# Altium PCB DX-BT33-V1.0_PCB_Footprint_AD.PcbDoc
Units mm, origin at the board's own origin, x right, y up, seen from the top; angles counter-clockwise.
Board outline 152.4 x 101.6 mm, 2 copper layers (Top Layer, Bottom Layer); 1 components, 15 nets, 26 pads, 0 vias.
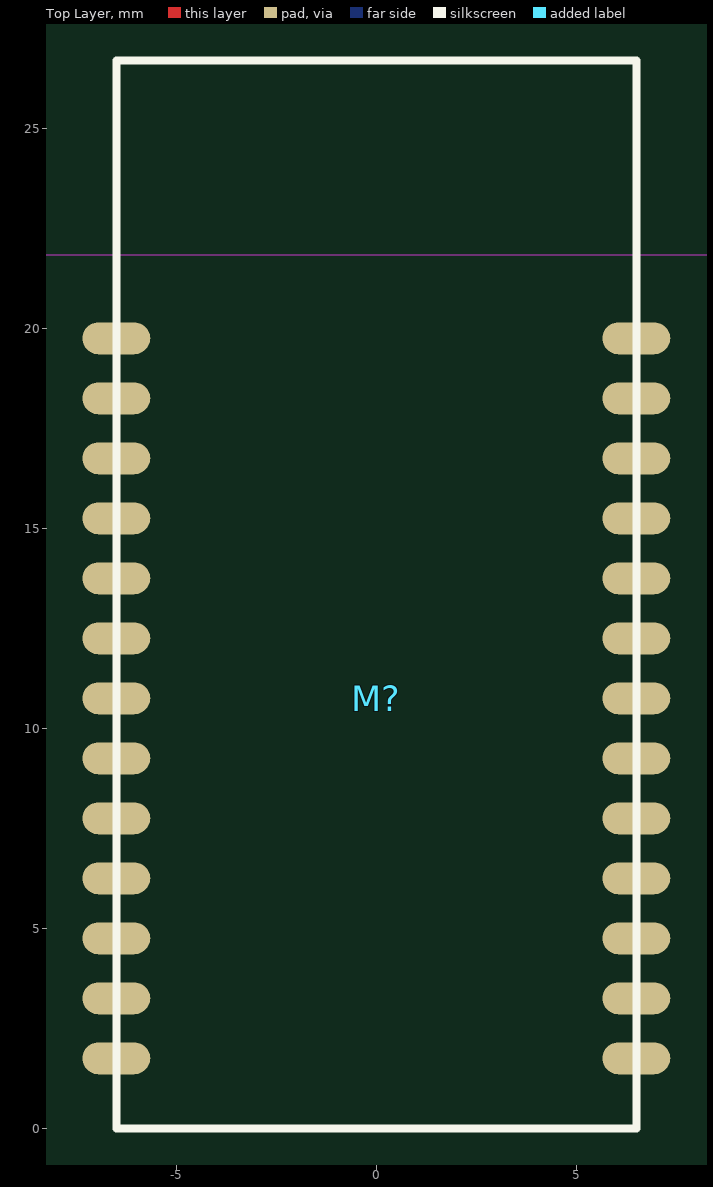
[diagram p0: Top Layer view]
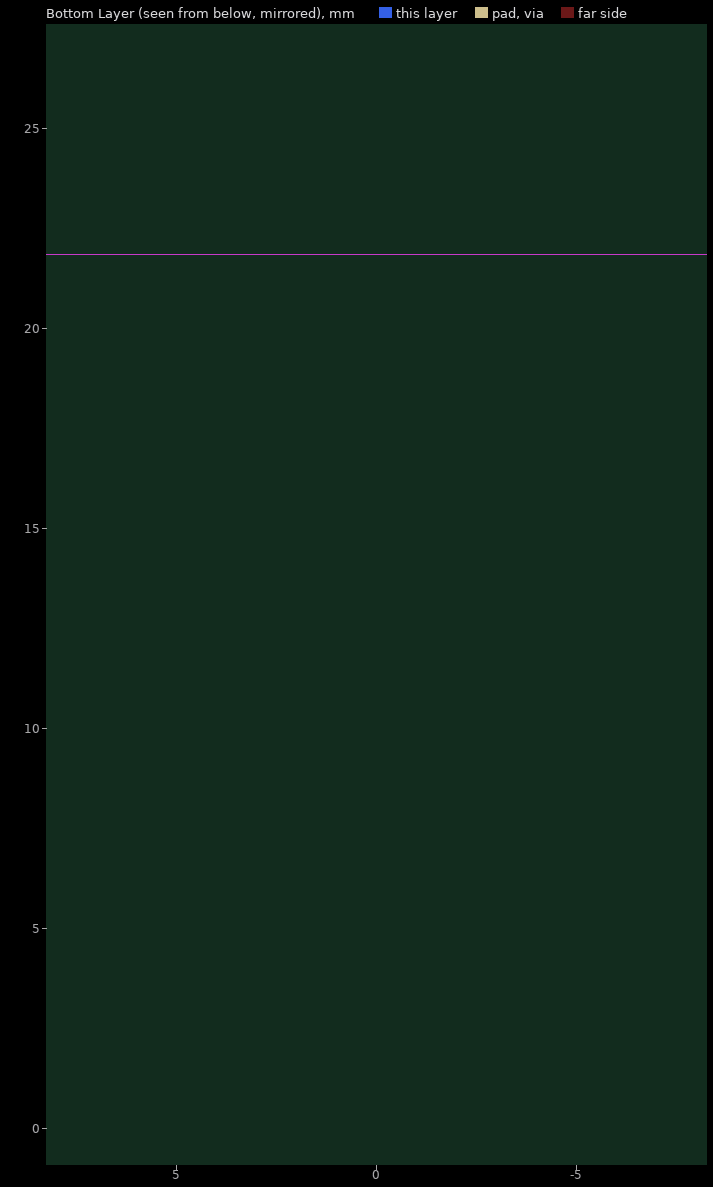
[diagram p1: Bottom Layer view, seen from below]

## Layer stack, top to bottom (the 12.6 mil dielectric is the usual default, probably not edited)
Top Solder: solder mask 0.0102, Solder Resist, Dk 3.5
Top Layer: signal copper 0.0356
Dielectric 1: dielectric 0.32, FR-4, Dk 4.8
Bottom Layer: signal copper 0.0356
Bottom Solder: solder mask 0.0102, Solder Resist, Dk 3.5

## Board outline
-72.857,-39.865 79.543,-39.865 79.543,61.735 -72.857,61.735

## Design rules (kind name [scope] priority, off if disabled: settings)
Clearance [All] p1: gap=0.254 ignorepadtopadclearanceinfootprint=FALSE except(0: Arc-Hole Track-Hole SMDPad-Hole THPad-Hole Via-Hole Fill-Hole Poly-Hole Region-Hole Text-Hole)
PolygonConnect [All] p1: connectstyle=Relief reliefconductorwidth=0.254 reliefentries=4 polygonreliefangle="90 Angle" airgapwidth=0.254
RoutingVias [All] p1: holewidth=0.711 width=1.27 viastyle="Through Hole" minholewidth=0.711 minwidth=1.27 maxholewidth=0.711 maxwidth=1.27
SolderMaskExpansion [All] p1: expansion=0.102 istentingtop=FALSE
Width [All] p1: maxlimit=0.254 minlimit=0.254 preferedwidth=0.254
30 further rules are at their usual default settings.

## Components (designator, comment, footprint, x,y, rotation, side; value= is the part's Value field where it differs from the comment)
M? "DX-BT33" DX-BT33 0,0 r0 top

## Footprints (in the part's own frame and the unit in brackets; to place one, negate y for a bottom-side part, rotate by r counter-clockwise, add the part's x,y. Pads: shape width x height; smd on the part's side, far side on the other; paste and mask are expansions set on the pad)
DX-BT33 [mm]
  oval 1.7x0.8 smd: 1(-6.5,19.75) 2(-6.5,18.25) 3(-6.5,16.75) 4(-6.5,15.25) 5(-6.5,13.75) 6(-6.5,12.25) 7(-6.5,10.75) 8(-6.5,9.25) 9(-6.5,7.75) 10(-6.5,6.25) 11(-6.5,4.75) 12(-6.5,3.25) 13(-6.5,1.75) 14(6.5,1.75) 15(6.5,3.25) 16(6.5,4.75) 17(6.5,6.25) 18(6.5,7.75) 19(6.5,9.25) 20(6.5,10.75) 21(6.5,12.25) 22(6.5,13.75) 23(6.5,15.25) 24(6.5,16.75) 25(6.5,18.25) 26(6.5,19.75)
  Keep-Out Layer region: -8.636,21.844 8.509,21.844 8.509,28.956 -8.636,28.956
  silkscreen extent -6.5,0 6.5,26.7

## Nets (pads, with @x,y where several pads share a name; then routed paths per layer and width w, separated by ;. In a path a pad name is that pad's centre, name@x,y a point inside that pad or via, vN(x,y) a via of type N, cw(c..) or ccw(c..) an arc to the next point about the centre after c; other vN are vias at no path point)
ANT3: 
GND: 
P00/TX/D-: 
P01/RX/D+: 
P02: 
P03: 
P04: 
P05: 
P06: 
P07: 
P10: 
P11: 
P32: 
RSTN: 
VBAT: 
pads on no net: M?.1 M?.2 M?.3 M?.4 M?.5 M?.6 M?.7 M?.8 M?.9 M?.10 M?.11 M?.12 M?.13 M?.14 M?.15 M?.16 M?.17 M?.18 M?.19 M?.20 M?.21 M?.22 M?.23 M?.24 M?.25 M?.26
